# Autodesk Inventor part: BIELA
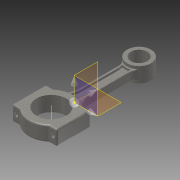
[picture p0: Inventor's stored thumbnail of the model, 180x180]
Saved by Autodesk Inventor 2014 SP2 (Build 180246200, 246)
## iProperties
Created: 2015-07
Part Number: BIELA
Material: Acero, fundido
Document SubType Name: Modeling
Designer: Jaime
Density: 6.71694 g/cm^3
Appearance: Acero - Fundido
Mass: 358.9 g
Surface Area: 208.044 cm^2
Volume: 53.4321 cm^3
Author: Jaime
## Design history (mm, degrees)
sketch "Boceto1"
  geometry: L1 (-7.625, 97.114)-(-7.625, 44.114); L2 (7.625, 97.114)-(7.625, 44.114); L3 (30, 22.714)-(30, -22.714); L4 (-30, -22.714)-(-30, 22.714); L5 (-30, 22.714)-(-20.683, 22.714); L6 (30, 22.714)-(20.683, 22.714); L7 (30, -22.714)-(20.683, -22.714); L8 (-20.683, -22.714)-(-30, -22.714); L9 (0, 0)-(0, 117.5); L10 (-5.576, 99.377)-(-5.24, 98.323); L11 (-4.625, 94.373)-(-4.625, 44.373); L12 (-5.807, 36.776)-(-6.953, 33.184); L13 (-5.696, 31.928)-(-4.558, 32.291); L14 (4.558, 32.291)-(5.696, 31.928); L15 (6.953, 33.184)-(5.807, 36.776); L16 (4.625, 44.373)-(4.625, 94.373); L17 (5.24, 98.323)-(5.576, 99.377); L18 (4.319, 100.633)-(4.558, 100.709); L19 (-4.319, 100.633)-(-4.558, 100.709); C1 r 20 at (0, 0); C2 r 11 at (0, 117.5); A1 r 16 centre (0, 117.5) between (11.379, 106.252) and (-11.379, 106.252); A2 r 25 centre (-32.625, 44.114) between (-16.273, 25.203) and (-7.625, 44.114); A3 r 13 centre (-20.625, 97.114) between (-7.625, 97.114) and (-11.379, 106.252); A4 r 25 centre (32.625, 44.114) between (7.625, 44.114) and (19.333, 22.94); A5 r 13 centre (20.625, 97.114) between (11.379, 106.252) and (7.625, 97.114); A6 r 30 centre (0, 0) between (-18.803, -23.376) and (18.803, -23.376); A7 r 3 centre (-20.683, 25.714) between (-20.683, 22.714) and (-18.803, 23.376); A8 r 3 centre (20.683, 25.714) between (18.803, 23.376) and (20.683, 22.714); A9 r 3 centre (20.683, -25.714) between (20.683, -22.714) and (18.803, -23.376); A10 r 3 centre (-20.683, -25.714) between (-18.803, -23.376) and (-20.683, -22.714); A11 r 13 centre (17.625, 94.373) between (5.24, 98.323) and (4.625, 94.373); A12 r 13 centre (-17.625, 94.373) between (-4.625, 94.373) and (-5.24, 98.323); A13 r 25 centre (29.625, 44.373) between (4.625, 44.373) and (5.807, 36.776); A14 r 25 centre (-29.625, 44.373) between (-5.807, 36.776) and (-4.625, 44.373); A15 r 15 centre (0, 115) between (-4.558, 100.709) and (4.558, 100.709); A16 r 15 centre (0, 18) between (4.558, 32.291) and (-4.558, 32.291); A17 r 1 centre (-6, 32.88) between (-6.953, 33.184) and (-5.696, 31.928); A18 r 1 centre (6, 32.88) between (5.696, 31.928) and (6.953, 33.184); A19 r 1 centre (4.623, 99.68) between (5.576, 99.377) and (4.319, 100.633); A20 r 1 centre (-4.623, 99.68) between (-4.319, 100.633) and (-5.576, 99.377); A21 r 30 centre (0, 0) between (18.803, 23.376) and (16.273, 25.203); A22 r 30 centre (0, 0) between (-16.273, 25.203) and (-18.803, 23.376); 8 further points
  constraints: 47 point on circle, 38 end point, 32 tangent, 24 centre point, 10 point on line, 8 equal radius, 8 parallel, 5 perpendicular, 3 coincident, 1 collinear, 1 horizontal alignment, 1 midpoint, 1 vertical, 1 vertical alignment, 8 other
  dimensions: "d0" = 40 diameter of C1; "d1" = 22 diameter of C2; "d2" = 117.5 distance of point (0, 0) C2.centre; "d3" = 7.625 distance from line of point (0, 0) L1; "d7" = 32 diameter of A1; "d9" = 13 radius of A3; "d10" = 25 radius of A2; "d11" = 15.25 distance between parallel lines of L2 L1; "d12" = 13 radius of A5; "d13" = 25 radius of A4; "d15" = 45.4275 distance of L3.start L3.end; "d16" = 3 radius of A7; "d18" = 30 radius of A6; "d19" = 60 distance between parallel lines of L3 L4; "d23" = 13 radius of A11; "d24" = 25 radius of A13; "d25" = 15 radius of A15; "d26" = 1 radius of A17; "d27" = 1 radius of A19; "d28" = 18 distance of L9.start A16.centre; "d29" = 2.5 distance of L9.end A15.centre; "d30" = 3 distance between parallel lines of L1 L11; "d31" = 50 distance of L16.start L16.end; "d32" = 66.8 vertical distance of A18.centre A19.centre; "d33" = 12 distance of A18.centre A17.centre
sketch "Boceto2"
  geometry: L1 (-5.576, 99.377)-(-5.24, 98.323); L2 (4.319, 100.633)-(4.558, 100.709); L3 (-4.319, 100.633)-(-4.558, 100.709); L4 (-4.625, 94.373)-(-4.625, 44.373); L5 (4.625, 44.373)-(4.625, 94.373); L6 (-7.625, 97.114)-(-7.625, 44.114); L7 (7.625, 97.114)-(7.625, 44.114); L8 (0, 0)-(0, 117.5); L9 (6.953, 33.184)-(5.807, 36.776); L10 (-30, 22.714)-(-20.683, 22.714); L11 (30, 22.714)-(20.683, 22.714); L12 (30, 22.714)-(30, -22.714); L13 (-30, -22.714)-(-30, 22.714); L14 (30, -22.714)-(20.683, -22.714); L15 (-20.683, -22.714)-(-30, -22.714); L16 (5.24, 98.323)-(5.576, 99.377); L17 (4.558, 32.291)-(5.696, 31.928); L18 (-5.696, 31.928)-(-4.558, 32.291); L19 (-5.807, 36.776)-(-6.953, 33.184); C1 r 20 at (0, 0); C2 r 11 at (0, 117.5); A1 r 13 centre (-17.625, 94.373) between (-4.625, 94.373) and (-5.24, 98.323); A2 r 13 centre (17.625, 94.373) between (5.24, 98.323) and (4.625, 94.373); A3 r 15 centre (0, 115) between (-4.558, 100.709) and (4.558, 100.709); A4 r 1 centre (-4.623, 99.68) between (-4.319, 100.633) and (-5.576, 99.377); A5 r 13 centre (-20.625, 97.114) between (-7.625, 97.114) and (-11.379, 106.252); A6 r 1 centre (4.623, 99.68) between (5.576, 99.377) and (4.319, 100.633); A7 r 1 centre (6, 32.88) between (5.696, 31.928) and (6.953, 33.184); A8 r 25 centre (29.625, 44.373) between (4.625, 44.373) and (5.807, 36.776); A9 r 3 centre (20.683, 25.714) between (18.803, 23.376) and (20.683, 22.714); A10 r 25 centre (32.625, 44.114) between (7.625, 44.114) and (19.333, 22.94); A11 r 25 centre (-32.625, 44.114) between (-16.273, 25.203) and (-7.625, 44.114); A12 r 30 centre (0, 0) between (-18.803, -23.376) and (18.803, -23.376); A13 r 3 centre (20.683, -25.714) between (20.683, -22.714) and (18.803, -23.376); A14 r 3 centre (-20.683, -25.714) between (-18.803, -23.376) and (-20.683, -22.714); A15 r 16 centre (0, 117.5) between (-11.379, 106.252) and (11.379, 106.252); A16 r 13 centre (20.625, 97.114) between (11.379, 106.252) and (7.625, 97.114); A17 r 25 centre (-29.625, 44.373) between (-5.807, 36.776) and (-4.625, 44.373); A18 r 15 centre (0, 18) between (4.558, 32.291) and (-4.558, 32.291); A19 r 30 centre (0, 0) between (18.803, 23.376) and (-18.803, 23.376); A20 r 3 centre (-20.683, 25.714) between (-20.683, 22.714) and (-18.803, 23.376); A21 r 1 centre (-6, 32.88) between (-6.953, 33.184) and (-5.696, 31.928); 9 further points
  constraints: 48 point on circle, 38 end point, 34 tangent, 23 centre point, 10 point on line, 8 equal radius, 8 parallel, 5 perpendicular, 3 coincident, 1 collinear, 1 horizontal alignment, 1 midpoint, 1 vertical, 1 vertical alignment, 8 other
  dimensions: "d34" = 40 diameter of C1; "d35" = 22 diameter of C2; "d36" = 117.5 distance of point (0, 0) C2.centre; "d37" = 7.625 distance from line of point (0, 0) L6; "d38" = 32 diameter of A15; "d39" = 13 radius of A5; "d40" = 25 radius of A11; "d41" = 15.25 distance between parallel lines of L7 L6; "d42" = 13 radius of A16; "d43" = 25 radius of A10; "d44" = 45.4275 distance of L11.start L12.end; "d45" = 3 radius of A20; "d46" = 30 radius of A19; "d47" = 30 radius of A12; "d48" = 60 distance between parallel lines of L12 L13; "d49" = 53 distance of L7.start L7.end; "d50" = 53 distance of L6.start L6.end; "d51" = 13 radius of A2; "d52" = 25 radius of A8; "d53" = 15 radius of A3; "d54" = 1 radius of A21; "d55" = 1 radius of A6; "d56" = 18 distance of L8.start A18.centre; "d57" = 2.5 distance of L8.end A3.centre; "d58" = 3 distance between parallel lines of L6 L4; "d59" = 50 distance of L5.start L5.end; "d60" = 66.8 vertical distance of A7.centre A6.centre; "d61" = 12 distance of A7.centre A21.centre
extrude "Extrusión1" new body sketch "Boceto2" stored distance "d62" = 20; taper "d63" = 0 deg
extrude "Extrusión2" join sketch "Boceto1" stored distance "d64" = 6; taper "d65" = 0 deg
sketch "Boceto4"
  geometry: L1 (4.319, 100.633)-(4.558, 100.709); L2 (-5.576, 99.377)-(-5.24, 98.323); L3 (30, -22.714)-(20.683, -22.714); L4 (30, 22.714)-(30, -22.714); L5 (-30, -22.714)-(-30, 22.714); L6 (30, 22.714)-(20.683, 22.714); L7 (-30, 22.714)-(-20.683, 22.714); L8 (4.558, 32.291)-(5.696, 31.928); L9 (-5.807, 36.776)-(-6.953, 33.184); L10 (6.953, 33.184)-(5.807, 36.776); L11 (-5.696, 31.928)-(-4.558, 32.291); L12 (5.24, 98.323)-(5.576, 99.377); L13 (-4.319, 100.633)-(-4.558, 100.709); L14 (4.625, 44.373)-(4.625, 94.373); L15 (7.625, 97.114)-(7.625, 44.114); L16 (-4.625, 94.373)-(-4.625, 44.373); L17 (-7.625, 97.114)-(-7.625, 44.114); L18 (0, 0)-(0, 117.5); L19 (-20.683, -22.714)-(-30, -22.714); C1 r 20 at (0, 0); C2 r 11 at (0, 117.5); A1 r 13 centre (17.625, 94.373) between (5.24, 98.323) and (4.625, 94.373); A2 r 13 centre (-17.625, 94.373) between (-4.625, 94.373) and (-5.24, 98.323); A3 r 3 centre (20.683, -25.714) between (20.683, -22.714) and (18.803, -23.376); A4 r 30 centre (0, 0) between (-18.803, -23.376) and (18.803, -23.376); A5 r 30 centre (0, 0) between (-16.273, 25.203) and (-18.803, 23.376); A6 r 3 centre (-20.683, 25.714) between (-20.683, 22.714) and (-18.803, 23.376); A7 r 3 centre (-20.683, -25.714) between (-18.803, -23.376) and (-20.683, -22.714); A8 r 13 centre (-20.625, 97.114) between (-7.625, 97.114) and (-11.379, 106.252); A9 r 30 centre (0, 0) between (18.803, 23.376) and (16.273, 25.203); A10 r 3 centre (20.683, 25.714) between (18.803, 23.376) and (20.683, 22.714); A11 r 16 centre (0, 117.5) between (11.379, 106.252) and (-11.379, 106.252); A12 r 13 centre (20.625, 97.114) between (11.379, 106.252) and (7.625, 97.114); A13 r 25 centre (32.625, 44.114) between (7.625, 44.114) and (19.333, 22.94); A14 r 1 centre (4.623, 99.68) between (5.576, 99.377) and (4.319, 100.633); A15 r 15 centre (0, 115) between (-4.558, 100.709) and (4.558, 100.709); A16 r 1 centre (-4.623, 99.68) between (-4.319, 100.633) and (-5.576, 99.377); A17 r 25 centre (-32.625, 44.114) between (-16.273, 25.203) and (-7.625, 44.114); A18 r 25 centre (29.625, 44.373) between (4.625, 44.373) and (5.807, 36.776); A19 r 25 centre (-29.625, 44.373) between (-5.807, 36.776) and (-4.625, 44.373); A20 r 15 centre (0, 18) between (4.558, 32.291) and (-4.558, 32.291); A21 r 1 centre (-6, 32.88) between (-6.953, 33.184) and (-5.696, 31.928); A22 r 1 centre (6, 32.88) between (5.696, 31.928) and (6.953, 33.184); 9 further points
  constraints: 47 point on circle, 38 end point, 32 tangent, 24 centre point, 10 point on line, 8 equal radius, 8 parallel, 5 perpendicular, 3 coincident, 1 collinear, 1 horizontal alignment, 1 midpoint, 1 vertical, 1 vertical alignment, 8 other
  dimensions: "d66" = 40 diameter of C1; "d67" = 22 diameter of C2; "d68" = 117.5 distance of point (0, 0) C2.centre; "d69" = 7.625 distance from line of point (0, 0) L17; "d70" = 32 diameter of A11; "d71" = 13 radius of A8; "d72" = 25 radius of A17; "d73" = 15.25 distance between parallel lines of L15 L17; "d74" = 13 radius of A12; "d75" = 25 radius of A13; "d76" = 45.4275 distance of L4.start L3.start; "d77" = 3 radius of A6; "d78" = 30 radius of A4; "d79" = 60 distance between parallel lines of L4 L5; "d80" = 53 distance of L15.start L15.end; "d81" = 53 distance of L17.start L17.end; "d82" = 13 radius of A1; "d83" = 25 radius of A18; "d84" = 15 radius of A15; "d85" = 1 radius of A21; "d86" = 1 radius of A14; "d87" = 18 distance of L18.start A20.centre; "d88" = 2.5 distance of L18.end A15.centre; "d89" = 3 distance between parallel lines of L17 L16; "d90" = 50 distance of L14.start L14.end; "d91" = 66.8 vertical distance of A22.centre A14.centre; "d92" = 12 distance of A22.centre A21.centre
extrude "Extrusión3" join sketch "Boceto4" stored distance "d93" = 11.6; taper "d94" = 0 deg
fillet "Empalme1" dims "d95" = 1
fillet "Empalme2" dims "d96" = 2
node "Eje de trabajo1"
node "Plano de corte de biela"
feature "Dividir1"
  node "Sólido1"
node "Punto de trabajo1"
node "Punto de trabajo2"
hole "Hole1" diameter "d99" = 5; stored, may be unused: countersink angle "d103" = 90 deg, drill point angle "d105" = 118 deg; dims "d100" = 6, "d101" = 4, "d102" = 2, "d104" = 8, "d106" = 10, "d107" = 10
hole "Hole2" diameter "d110" = 5; stored, may be unused: countersink angle "d114" = 90 deg, drill point angle "d116" = 118 deg; dims "d108" = 10, "d109" = 10, "d111" = 6, "d112" = 4, "d113" = 2, "d115" = 51.75
fillet "Empalme3" dims "d117" = 1
node "Sólido2"
node "Sólido3"
